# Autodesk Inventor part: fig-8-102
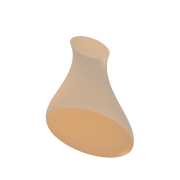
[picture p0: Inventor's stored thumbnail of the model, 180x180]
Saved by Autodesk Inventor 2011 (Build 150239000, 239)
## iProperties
Created: 2004-05
Part Number: fig-8-102
Document SubType Name: Modeling
Designer: CADCIM Technologies
Manufacturer: Standard
Standards Organization: Custom
Density: 1 g/cm^3
Author: CADCIM Technologies
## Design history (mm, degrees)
sketch "Sketch4"
  geometry: 1 further point; 1 other entity
  constraints: 2 other
workplane "Work Plane2"
sketch "Sketch5"
  geometry: 1 further point; 1 other entity
  constraints: 2 other
feature "LoftSrf1" sketch "Sketch5" dims "d4" = 20, "d5" = 110 deg, "d6" = 40, "d7" = 70 deg
patch "Boundary Patch1" dims "d8" = 0, "d9" = 0
patch "Boundary Patch2" dims "d10" = 0, "d11" = 0
patch "Boundary Patch3" dims "d12" = 0, "d13" = 0
body "Srf1"
body "Srf2"
body "Srf3"
body "Srf4"
other parameters: "d3" = 33.5
